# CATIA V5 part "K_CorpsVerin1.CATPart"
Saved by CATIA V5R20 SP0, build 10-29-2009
Part number: Corps_verin1
Bounding box of the stored display mesh (mm): x -5.904 to 5.904, y 12.749 to 124.647, z 163.898 to 176.811
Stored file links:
  G:\Khaled_CFAO_2011\ST2M\ST2M_GR1\hgrenier\Khaled\CAD_ThinkMOTION\K_CorpsVerin1.CATPart
  C:\Users\Tom\Documents\Cours 2A\CFAO\Projet thinkmotion\Hugo\porte_outil.CATProduct
  G:\Khaled_CFAO_2011\ST2M\ST2M_GR1\hgrenier\Khaled\CAD_ThinkMOTION\K_Squelette.CATPart
  G:\Khaled_CFAO_2011\ST2M\ST2M_GR1\hgrenier\Khaled\CAD_ThinkMOTION\K_Bras.CATPart
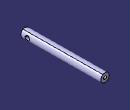
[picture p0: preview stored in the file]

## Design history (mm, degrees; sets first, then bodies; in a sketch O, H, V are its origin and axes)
Parameters
  diametre_trou_bras_verin1 = 6 mm
Set1
  Plane1 "plan_sym": linked copy from another document
  Point1 "Centre_verin/bielle2": linked copy from another document
  Point2 "Centre_bras_verin1": linked copy from another document
  DatumSurface1: linked copy from another document
Body1 (main body)
  Sketch1 on Plane1, origin (0, 0, 0), H (0, 1, 0), V (0, 0, 1)
    axis line L1 (21.719, 169.887) -> (184.816, 171.511)
    point P1 (21.719, 169.887)
    point P2 (184.816, 171.511)
    reference projected point E1 (184.816, 171.511) from Point1
    reference projected point E2 (21.719, 169.887) from Point2
    line L2 (124.5294, 176.8149) -> (12.7491, 175.7019)
    line L3 (12.7491, 175.7019) -> (12.7865, 171.9477)
    line L4 (12.7865, 171.9477) -> (124.5668, 173.0607)
    line L5 (124.5668, 173.0607) -> (124.5294, 176.8149)
    coincidence: P2 E1, P1 E2
    parallelism: L2 L1, L5 L3, L2 L4
    perpendicularity: L2 L3
  Shaft1: profile Sketch1, axis Sketch1.L1, angle 360
  Sketch2 on Plane1, origin (0, 0, 0), H (0, 1, 0), V (0, 0, 1)
    circle A1 centre (21.719, 169.887) radius 3
    point P1 (21.719, 169.887)
    reference projected point E1 (21.719, 169.887) from Point2
    radius A1 = 3 {= diametre_trou_bras_verin1 /2}
    coincidence: P1 E1
  Pocket1: profile Sketch2, direction (-1, 0, 0), length 20, mirrored extent
  Sketch3 on face of DatumSurface1, origin (14, 0, 0), H (0, 1, 0), V (0, 0, 1)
